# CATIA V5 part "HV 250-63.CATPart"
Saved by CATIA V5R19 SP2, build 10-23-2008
Part number: HV 250-63
Bounding box of the stored display mesh (mm): x -18.951 to 18.951, y -18.952 to 18.952, z 0.053 to 196
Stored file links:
  C:\Users\Bora\Desktop\3D KATI MODEL- CATIA PART\HV serisi\HV 250\HV 250-63.CATPart
  C:\Program Files\Dassault Systemes\B19\intel_a\reffiles\standard\MetricThickPitch.txt
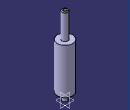
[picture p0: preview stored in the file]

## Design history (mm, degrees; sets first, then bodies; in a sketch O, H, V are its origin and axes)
Body1 (main body)
  Sketch1 on yz-plane, origin (0, 0, 0), H (0, 1, 0), V (0, 0, 1)
    point P1 (7.5, 194)
    point P3 (7.5, 194)
    point P7 (6, 17)
    point P8 (6, 1)
    point P10 (6, 1)
    point P12 (6, 17)
    line L1 (7.5, 194) -> (7.5, 132)
    arc A1 centre (5.5, 194) radius 2 from (7.5, 194) to (5.5, 196) ccw
    line L2 (6, 17) -> (6, 1)
    line L3 (5, 0) -> (6, 1)
    arc A2 centre (6, 18) radius 1 from (6, 19) to (6, 17) ccw
    line L4 (6, 19) -> (19, 19)
    line L5 (5, 0) -> (0, 0)
    line L6 (19, 132) -> (7.5, 132)
    line L7 (5.5, 196) -> (0, 196)
    point P13 (0, 196)
    line L8 (19, 132) -> (19, 19)
    horizontal: L4 H, L5 H, L6 H
    coincidence: P13 V, P1 P3, P7 P12, P8 P10
    tangency: L7 A1
    vertical: L8 V
  Shaft1: profile Sketch1, axis Sketch1.V, angle 360
  Sketch2 on face of Shaft1 from Sketch1.L5, origin (0, 0, 0), H (1, 0, 0), V (0, -1, 0)
    point P1 (0, 0)
  Hole1: placed by Sketch2, at (0, 0, 0) direction (0, 0, 1), diameter 10.106, depth 19, threaded "M12", thread diameter 12, thread depth 19, pitch 1.75
  Sketch3 on face of Shaft1 from Sketch1.L7, origin (0, 0, 196), H (1, 0, 0), V (0, 1, 0)
    point P1 (0, 0)
  Hole2: placed by Sketch3, at (0, 0, 196) direction (0, 0, -1), diameter 6.647, depth 15, threaded "M8", thread diameter 8, thread depth 15, pitch 1.25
